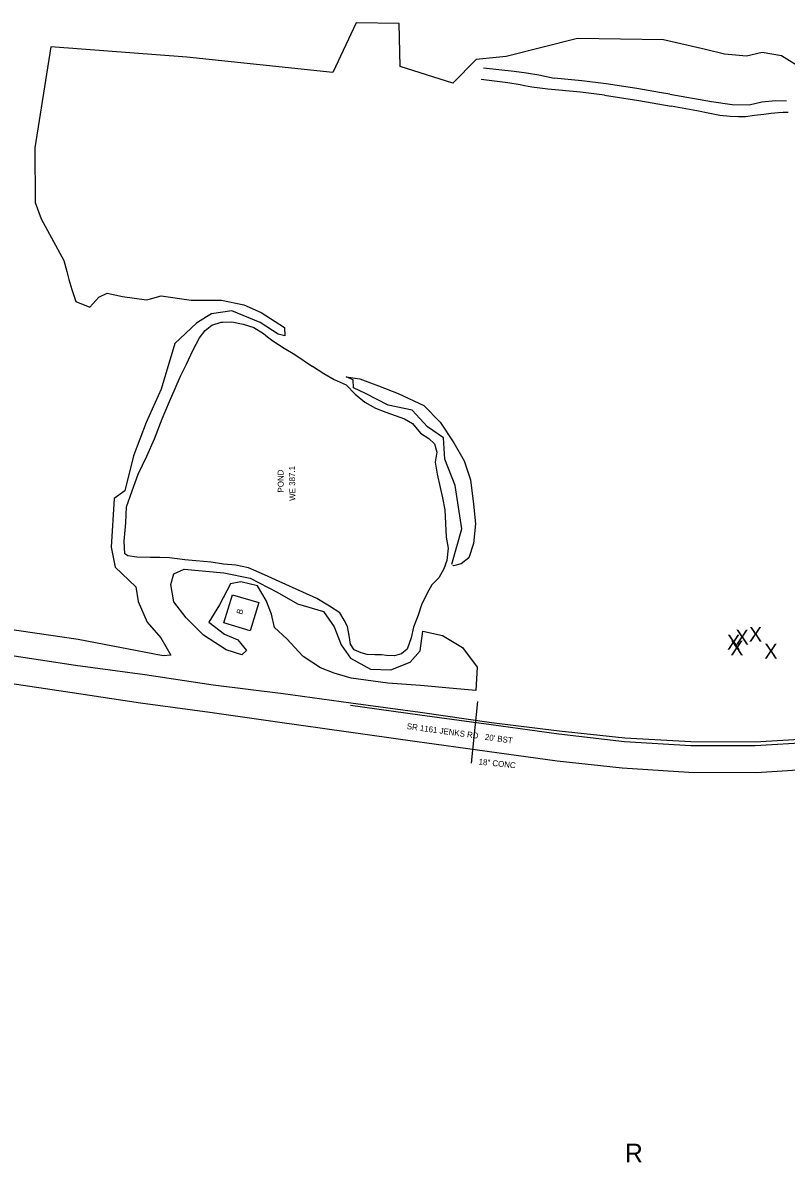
# Model space of a CAD drawing. Extents: x 2030130 to 2036320, y 723205 to 762423.
# Drawn here: x 2031702 to 2032217, y 729339 to 730108 of the extents above; entities that cross this region are included whole.
import ezdxf

# ---------------------------------------------------------------- set-up
doc = ezdxf.new("R2010")
doc.units = 0
for name, color, linetype in [('Draft_Station Labels Major', 7, 'Continuous'), ('Draft_Station Tics Major', 7, 'Continuous'), ('Draft_Station Tics Minor', 7, 'Continuous'), ('Exist Terrain Model Ground Surface', 7, 'Continuous'), ('Old_Level_23', 7, 'Continuous'), ('Old_Level_26', 7, 'Continuous'), ('Old_Level_28', 7, 'Continuous'), ('Prop Alignment Horizontal', 7, 'Continuous'), ('Prop Alignment Vertical', 7, 'Continuous'), ('Prop Horizontal Alignment Ramp', 7, 'Continuous')]:
    doc.layers.add(name, color=color, linetype=linetype)

msp = doc.modelspace()

# ---------------------------------------------------------------- linework, layer by layer
at = {"layer": 'Draft_Station Labels Major'}
for points in [[(2032012.67, 730078.05), (2032033.44, 730075.8), (2032041.86, 730074.69), (2032050.04, 730073.25), (2032060.42, 730071.09)], [(2032056.22, 730063.64), (2032045.48, 730064.88), (2032040.4, 730065.76), (2032037.6, 730066.38), (2032029.16, 730067.9), (2032011.15, 730070.11)], [(2032131.7, 730061.39), (2032116.33, 730063.99), (2032095.54, 730067.21), (2032079.1, 730069.28), (2032060.42, 730071.09)], [(2032094.46, 730059.47), (2032078.24, 730061.51), (2032056.22, 730063.64)], [(2032094.46, 730059.47), (2032117.66, 730055.8), (2032139.46, 730052.11)], [(2032138.66, 730060.13), (2032131.7, 730061.39)], [(2032138.66, 730060.13), (2032166.77, 730055.21), (2032180.76, 730053.18), (2032192.12, 730052.97), (2032200.79, 730054.97), (2032209.87, 730055.98), (2032217.39, 730055.57)], [(2032218.51, 730047.82), (2032214.99, 730047.89), (2032212, 730047.51), (2032206.9, 730047.03), (2032201.99, 730046.48), (2032195.76, 730045.72), (2032189.73, 730044.96), (2032184.88, 730044.81), (2032179.36, 730045.05), (2032172.31, 730045.87), (2032165.64, 730047.22), (2032156.71, 730048.87), (2032139.46, 730052.11)], [(2031595.92, 729695.52), (2031642.75, 729688.46), (2031690.09, 729681.69), (2031737.24, 729674.61), (2031784.05, 729668.19), (2031830.36, 729661.32), (2031877.54, 729655.39), (2031923.27, 729649.02), (2031970.03, 729642.76), (2032018.07, 729635.84)], [(2032316.86, 729616.02), (2032270.47, 729608.33), (2032235.41, 729604.35), (2032197.13, 729601.93), (2032151.49, 729601.97), (2032106.34, 729604.99), (2032062.45, 729609.73), (2032015.17, 729616.16), (2031966.44, 729623), (2031920.16, 729629.46), (2031875.29, 729635.9), (2031827.97, 729642.57), (2031781.22, 729648.88), (2031734.97, 729655.88), (2031688.46, 729662.82), (2031640.63, 729670.12), (2031593.1, 729677.15)], [(2031923.04, 729647.61), (2031969.69, 729641.1), (2032017.84, 729634.43), (2032017.84, 729634.43), (2032063.72, 729628.11), (2032107.96, 729622.91), (2032152.66, 729620.24), (2032196.3, 729620.29), (2032233.74, 729622.6), (2032267.72, 729626.52), (2032313.65, 729634.04)], [(2032018.07, 729635.84), (2032063.82, 729630.2), (2032108.12, 729625.41), (2032152.74, 729622.95), (2032196.2, 729622.76), (2032233.57, 729624.96), (2032267.32, 729629.03), (2032313.12, 729636.71)]]:
    msp.add_lwpolyline(points, dxfattribs=at)
at = {"layer": 'Draft_Station Tics Major'}
for points in [[(2032134.25, 730096.85), (2032076.33, 730097.86), (2032028.04, 730085.6), (2032007.89, 730083.57), (2031992.03, 730067.57), (2031956.57, 730078.92), (2031955.88, 730107.94), (2031926.9, 730108.38), (2031911.12, 730074.81), (2031812.57, 730085.12), (2031720.59, 730092.07), (2031709.88, 730024.03), (2031710.1, 729987.03)], [(2032377.29, 729895.73), (2032373.58, 729902.22), (2032371.36, 729920.03), (2032368.24, 729938.33), (2032359.14, 729956.91), (2032351.91, 729977.43), (2032348.14, 729988.43), (2032342.68, 729996.3), (2032331.65, 730010.64), (2032321.82, 730016.9), (2032306.17, 730028.77), (2032290.74, 730035.58), (2032272.4, 730045), (2032256.17, 730055.47), (2032251.01, 730061.58), (2032237.41, 730070.28), (2032225.88, 730078.56), (2032213.9, 730086.09), (2032200.87, 730088.34), (2032190.26, 730085.77), (2032175.58, 730087.26), (2032162.67, 730090.45), (2032134.25, 730096.85)], [(2031710.1, 729987.03), (2031714.11, 729976.02), (2031721.04, 729963.15), (2031729.52, 729947.89), (2031731.43, 729940.36)], [(2031731.43, 729940.36), (2031732.78, 729935.02), (2031734.87, 729928.3), (2031737.58, 729920.08), (2031746.9, 729916.32), (2031753.08, 729923.06), (2031758.8, 729925.72), (2031769.01, 729923.48), (2031785.19, 729921.35), (2031787.89, 729922.06)], [(2031787.89, 729922.06), (2031795.12, 729923.96), (2031815.51, 729920.99), (2031835.92, 729921.17), (2031850.87, 729917.97), (2031862.71, 729912.74), (2031878.32, 729902.66), (2031878.55, 729897.08), (2031874.2, 729898.18), (2031862.07, 729905.89), (2031850.44, 729910.6), (2031842.86, 729913.77), (2031829.03, 729911.86), (2031825.77, 729909.78)], [(2031825.77, 729909.78), (2031818.98, 729905.44), (2031804.43, 729891.76), (2031795.14, 729861.03), (2031785.1, 729838.53), (2031776.53, 729815.87), (2031770.57, 729792.22), (2031763.42, 729787.01), (2031761.3, 729754.34), (2031764.05, 729740.68), (2031777.99, 729727.52), (2031779.68, 729717.58), (2031785.65, 729703.58), (2031794.9, 729693.06), (2031801.61, 729681.24), (2031796.54, 729680.97), (2031739.03, 729691.79), (2031678.75, 729700.59)], [(2031991.36, 729742.73), (2031998.09, 729766.52), (2031993.75, 729795.97), (2031986.58, 729813.64), (2031985.74, 729828.19), (2031974.89, 729835.47), (2031964.51, 729846.68), (2031948.31, 729850.14), (2031933.07, 729858.13), (2031925.06, 729861.92), (2031924.88, 729867.31), (2031919.94, 729869.37), (2031929.28, 729867.96), (2031941.83, 729863.27), (2031955.25, 729858.01), (2031972.39, 729849.86), (2031983.56, 729838.71), (2031992.74, 729824.71), (2031999.72, 729812.57), (2032003.96, 729799.65), (2032005.97, 729783.29), (2032007.45, 729770.06), (2032005.93, 729756.71), (2032002.83, 729746.94), (2031997.65, 729743.04), (2031992.62, 729741.64), (2031991.96, 729742.15)], [(2031890.73, 729680.58), (2031880.08, 729692.26), (2031871.61, 729699.98), (2031869.6, 729709.06), (2031866.15, 729718.32), (2031860.17, 729728.21), (2031848.9, 729730.76), (2031841.94, 729729.43), (2031834.52, 729715.24), (2031827.22, 729703.56), (2031837.99, 729695.48), (2031846.83, 729691.65), (2031852.73, 729684.41), (2031849.57, 729681.47), (2031839.01, 729684.95), (2031823.67, 729694.83), (2031812.04, 729706.43), (2031803.64, 729717.37), (2031801.72, 729728.94), (2031803.62, 729736.13), (2031810.71, 729739.48), (2031837.48, 729736.85), (2031855.13, 729733.3), (2031873.4, 729723.9), (2031887.2, 729715.95), (2031904.68, 729710.69), (2031912.02, 729700.53), (2031916.57, 729688.21), (2031922.89, 729679.29), (2031936.45, 729671.78), (2031950.3, 729671.32), (2031963.28, 729676.63), (2031970.09, 729684.3), (2031971.78, 729697.62), (2031985.02, 729694.52), (2031998.56, 729686.5), (2032008.58, 729673.17), (2032007.69, 729657.4), (2031992.24, 729658.76), (2031970.29, 729660.72), (2031948.15, 729662.34), (2031923.35, 729665.7), (2031912, 729669.1), (2031902.68, 729672.73), (2031891, 729680.32)]]:
    msp.add_lwpolyline(points, dxfattribs=at)
at = {"layer": 'Draft_Station Tics Minor'}
msp.add_line((2032008.72, 729649.98), (2032004.51, 729608.46), dxfattribs=at)
at = {"layer": 'Exist Terrain Model Ground Surface'}
msp.add_lwpolyline([(2031843.24, 729722.15), (2031861.03, 729716.79), (2031855.29, 729697.71), (2031837.5, 729703.06)], close=True, dxfattribs=at)
at = {"layer": 'Prop Alignment Horizontal'}
for points in [[(2031897.39, 729876.48), (2031904.99, 729871.46), (2031911.86, 729867.41), (2031920.15, 729863.78), (2031926.14, 729857.55), (2031932.7, 729852.26), (2031939.89, 729848.01), (2031946.73, 729845.4), (2031953.17, 729843.1), (2031959.54, 729840.93), (2031964.82, 729837.77), (2031970.16, 729831.34), (2031975.97, 729827.72), (2031979.76, 729824.07), (2031981.17, 729818.42), (2031980.12, 729811.55), (2031981.38, 729803.54), (2031983.56, 729794.64), (2031985.19, 729787.62), (2031986.58, 729779.55), (2031987.08, 729770.22), (2031987.58, 729760.96), (2031988.82, 729753.61), (2031988.06, 729745.17), (2031985.94, 729739.59), (2031982.53, 729733.58), (2031977.92, 729728.73), (2031974.69, 729723.13), (2031970.85, 729715.29), (2031968.63, 729708.26), (2031965.58, 729700.24), (2031963.95, 729693.1), (2031961.16, 729685.34), (2031957.36, 729682.14), (2031952.75, 729680.95), (2031947.33, 729680.98), (2031943.8, 729681.5), (2031939.42, 729681.61), (2031934.26, 729681.85), (2031930.26, 729682.95), (2031925.39, 729684.82), (2031923.04, 729688.82), (2031922.15, 729694.61), (2031920.99, 729700.66), (2031918.63, 729704.93), (2031915.86, 729709.9), (2031908.79, 729714.34), (2031900.28, 729719.47), (2031890.8, 729723.93), (2031874.8, 729730.95), (2031864.93, 729735.67), (2031854.01, 729740.23), (2031845.62, 729742.1), (2031837.32, 729742.67), (2031828.81, 729744.01), (2031818.54, 729745), (2031811.09, 729745.64), (2031800.68, 729747.02), (2031794.15, 729747.29), (2031787.82, 729747.17), (2031778.68, 729747.4), (2031772.72, 729748.46), (2031770.6, 729749.67), (2031770.12, 729758.27), (2031771.33, 729770.76), (2031771.85, 729781.41), (2031775.63, 729792.32), (2031779.73, 729803.62), (2031785.39, 729815.61), (2031790.72, 729827.45), (2031795.82, 729840.93), (2031800.7, 729852.64), (2031804.65, 729861.33), (2031808.09, 729869.62), (2031812.31, 729877.92), (2031816.45, 729887), (2031821.06, 729895.51), (2031824.75, 729900.6), (2031829.39, 729904.21), (2031835.75, 729906.16), (2031836.86, 729906.19)], [(2031836.86, 729906.19), (2031842.8, 729906.35), (2031850.59, 729904.93), (2031857.68, 729902.71), (2031864.35, 729898.59), (2031867.05, 729896.4)], [(2031867.05, 729896.4), (2031870.58, 729893.55), (2031878.17, 729888.72), (2031885.5, 729884.29), (2031897.4, 729876.35)]]:
    msp.add_lwpolyline(points, dxfattribs=at)

# ---------------------------------------------------------------- texts
at = {"layer": 'Draft_Station Tics Major'}
for p in [(2032191.97, 729690.44), (2032177.19, 729685.1), (2032182.9, 729688.5), (2032179.36, 729681.11), (2032202.36, 729678.97)]:
    msp.add_text('X', height=10, dxfattribs=at).set_placement(p)
at = {"layer": 'Old_Level_23'}
msp.add_text("SR 1161 JENKS RD   20' BST", height=4, rotation=352.16307, dxfattribs=at).set_placement((2031960.78, 729631.46))
at = {"layer": 'Old_Level_26'}
msp.add_text('18" CONC', height=4, rotation=353.99523, dxfattribs=at).set_placement((2032009.31, 729607.49))
at = {"layer": 'Old_Level_28'}
msp.add_text('B', height=4, rotation=73.66432, dxfattribs=at).set_placement((2031849.71, 729708.5))
at = {"layer": 'Prop Alignment Vertical'}
for s, p in [('WE 387.1', (2031885.75, 729785.58)), ('POND', (2031877.92, 729791.21))]:
    msp.add_text(s, height=4, rotation=90.73533, dxfattribs=at).set_placement(p)
at = {"layer": 'Prop Horizontal Alignment Ramp'}
msp.add_text('R', height=12.5, dxfattribs=at).set_placement((2032108.24, 729338.88))

doc.saveas('drawing.dxf')
